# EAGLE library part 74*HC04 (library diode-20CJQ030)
SN54AHC04, SN74AHC04 HEX INVERTERS Features: Operating Range 2-V to 5.5-V VCC Latch-Up Performance Exceeds 250 mA PerJESD 17 ESD Protection Exceeds JESD 22 - 2000-V Human-Body Model (A114-A) - 200-V Machine Model (A115-A) - 1000-V Charged-Device Model (C101) Description: The MC74HC04A is identical in pinout to the LS04 and the MC14069. The device inputs are compatible with Standard CMOS outputs; with pullup resistors, they are compatible with LSTTL outputs. The device consists of six three?stage inverters. Features: Output Drive Capability: 10 LSTTL Loads Outputs Directly Interface to CMOS, NMOS and TTL Operating Voltage Range: 2.0 to 6.0 V Low Input Current: u1 A High Noise Immunity Characteristic of CMOS Devices In Compliance With the JEDEC Standard No. 7A Requirements Chip Complexity: 36 FETs or 9 Equivalent Gates Pb?Free Packages are Available* SN54HC04, SN74HC04 HEX INVERTERS Features: Wide Operating Voltage Range of 2 V to 6 V Outputs Can Drive Up To 10 LSTTL Loads Low Power Consumption, 20-uA Max ICC Typical tpd = 8 ns ±4-mA Output Drive at 5 V Low Input Current of 1 uA Max Please send any comments to: messi@users.sourceforge.net
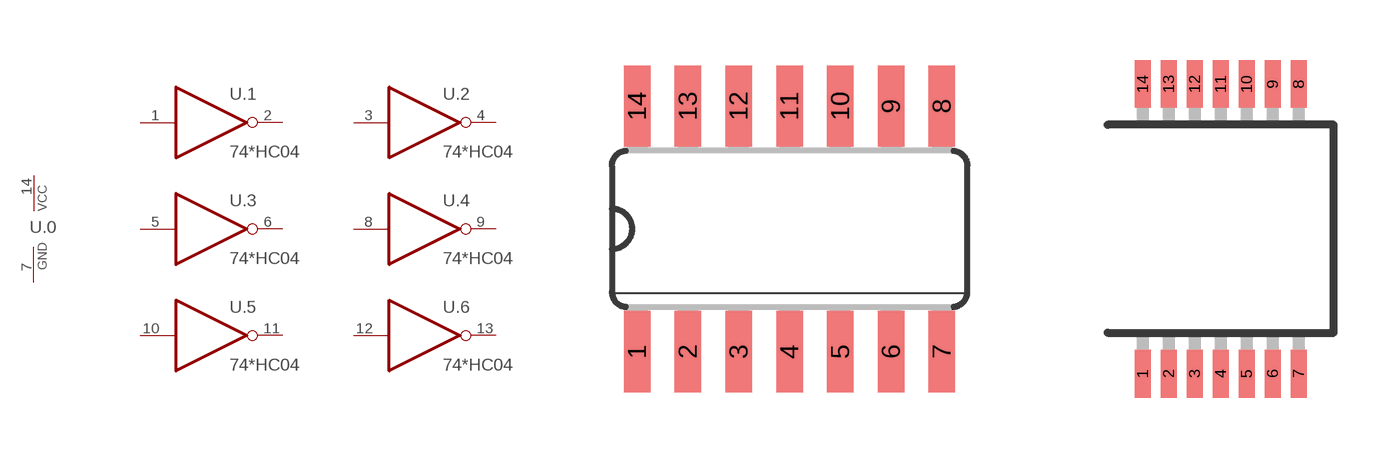
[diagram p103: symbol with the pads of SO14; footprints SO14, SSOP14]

Designator prefix U; gates .1=7404 .2=7404 .3=7404 .4=7404 .5=7404 .6=7404 .0=PWR_GND

## 74HC04D  [SO14]
1  .1:A  in
2  .1:Y  out
3  .2:A  in
4  .2:Y  out
5  .3:A  in
6  .3:Y  out
7  .0:GND  pwr
8  .4:A  in
9  .4:Y  out
10  .5:A  in
11  .5:Y  out
12  .6:A  in
13  .6:Y  out
14  .0:VCC  pwr

## 74HC04DB  [SSOP14]
Pads as for SO14

## 74HC04PW  [TSSOP14]
Pads as for SO14

## Footprint SO14 (pad centres in mm)
Small Outline package 150 mil
smd 0.66 x 2.032: 1 -3.81,-3.073; 2 -2.54,-3.073; 3 -1.27,-3.073; 4 0,-3.073; 5 1.27,-3.073; 6 2.54,-3.073; 7 3.81,-3.073; 8 3.81,3.073; 9 2.54,3.073; 10 1.27,3.073; 11 0,3.073; 12 -1.27,3.073; 13 -2.54,3.073; 14 -3.81,3.073

## Footprint SSOP14 (pad centres in mm)
smd 0.4 x 1.2: 1 -1.95,-3.625; 2 -1.3,-3.625; 3 -0.65,-3.625; 4 0,-3.625; 5 0.65,-3.625; 6 1.3,-3.625; 7 1.95,-3.625; 8 1.95,3.625; 9 1.3,3.625; 10 0.65,3.625; 11 0,3.625; 12 -0.65,3.625; 13 -1.3,3.625; 14 -1.95,3.625

## Footprint TSSOP14 (pad centres in mm)
Thin Shrink Small Outline Plastic 14
smd 0.35 x 1: 1 -1.95,-3; 2 -1.3,-3; 3 -0.65,-3; 4 0,-3; 5 0.65,-3; 6 1.3,-3; 7 1.95,-3; 8 1.95,3; 9 1.3,3; 10 0.65,3; 11 0,3; 12 -0.65,3; 13 -1.3,3; 14 -1.95,3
